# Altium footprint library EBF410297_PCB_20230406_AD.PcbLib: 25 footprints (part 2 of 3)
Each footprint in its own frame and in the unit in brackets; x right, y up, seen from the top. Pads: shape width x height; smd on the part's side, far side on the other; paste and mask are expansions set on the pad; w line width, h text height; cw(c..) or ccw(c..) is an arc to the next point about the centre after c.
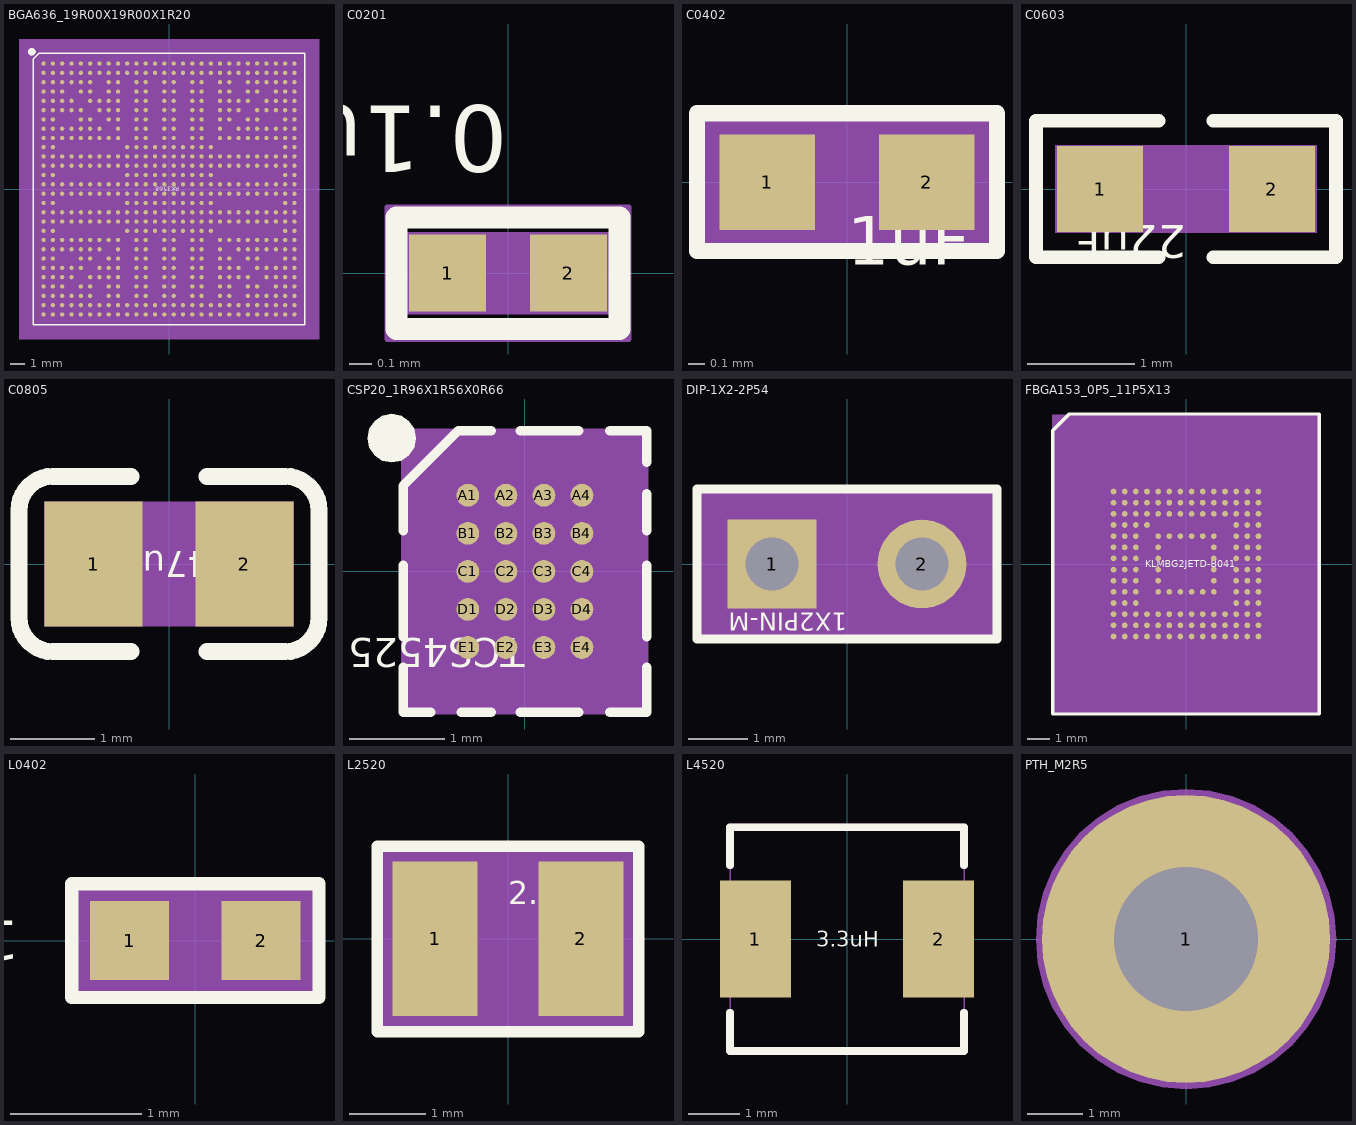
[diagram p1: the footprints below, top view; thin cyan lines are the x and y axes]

## BGA636_19R00X19R00X1R20 [mm] "BGA636_19R00X19R00X1R20"
pads (636):
  round 0.3 smd: A1(-8.78,8.78) A2(-8.13,8.78) A3(-7.48,8.78) A4(-6.82,8.78) A5(-6.17,8.78) A6(-5.52,8.78) A7(-4.87,8.78) A8(-4.22,8.78) A9(-3.57,8.78) A10(-2.93,8.78) A11(-2.28,8.78) A12(-1.63,8.78) A13(-0.98,8.78) A14(-0.33,8.78) A15(0.33,8.78) A16(0.98,8.78) A17(1.63,8.78) A18(2.28,8.78) A19(2.93,8.78) A20(3.57,8.78) A21(4.22,8.78) A22(4.87,8.78) A23(5.52,8.78) A24(6.17,8.78) A25(6.82,8.78) A26(7.48,8.78) A27(8.13,8.78) A28(8.78,8.78) AA1(-8.78,-4.22) AA2(-8.13,-4.22) AA3(-7.48,-4.22) AA4(-6.82,-4.22) AA5(-6.17,-4.22) AA6(-5.52,-4.22) AA7(-4.87,-4.22) AA9(-3.57,-4.22) AA11(-2.28,-4.22) AA12(-1.63,-4.22) AA14(-0.33,-4.22) AA15(0.33,-4.22) AA17(1.63,-4.22) AA18(2.28,-4.22) AA20(3.57,-4.22) AA22(4.87,-4.22) AA23(5.52,-4.22) AA24(6.17,-4.22) AA25(6.82,-4.22) AA26(7.48,-4.22) AA27(8.13,-4.22) AA28(8.78,-4.22) AB1(-8.78,-4.87) AB2(-8.13,-4.87) AB5(-6.17,-4.87) AB6(-5.52,-4.87) AB8(-4.22,-4.87) AB9(-3.57,-4.87) AB11(-2.28,-4.87) AB12(-1.63,-4.87) AB14(-0.33,-4.87) AB15(0.33,-4.87) AB17(1.63,-4.87) AB18(2.28,-4.87) AB20(3.57,-4.87) AB21(4.22,-4.87) AB23(5.52,-4.87) AB24(6.17,-4.87) AB27(8.13,-4.87) AB28(8.78,-4.87) AC1(-8.78,-5.52) AC2(-8.13,-5.52) AC3(-7.48,-5.52) AC4(-6.82,-5.52) AC5(-6.17,-5.52) AC7(-4.87,-5.52) AC8(-4.22,-5.52) AC9(-3.57,-5.52) AC11(-2.28,-5.52) AC12(-1.63,-5.52) AC14(-0.33,-5.52) AC15(0.33,-5.52) AC17(1.63,-5.52) AC18(2.28,-5.52) AC20(3.57,-5.52) AC21(4.22,-5.52) AC22(4.87,-5.52) AC24(6.17,-5.52) AC25(6.82,-5.52) AC26(7.48,-5.52) AC27(8.13,-5.52) AC28(8.78,-5.52) AD1(-8.78,-6.17) AD2(-8.13,-6.17) AD3(-7.48,-6.17) AD4(-6.82,-6.17) AD6(-5.52,-6.17) AD7(-4.87,-6.17) AD8(-4.22,-6.17) AD9(-3.57,-6.17) AD11(-2.28,-6.17) AD12(-1.63,-6.17) AD14(-0.33,-6.17) AD15(0.33,-6.17) AD17(1.63,-6.17) AD18(2.28,-6.17) AD20(3.57,-6.17) AD21(4.22,-6.17) AD22(4.87,-6.17) AD23(5.52,-6.17) AD25(6.82,-6.17) AD26(7.48,-6.17) AD27(8.13,-6.17) AD28(8.78,-6.17) AE1(-8.78,-6.82) AE2(-8.13,-6.82) AE3(-7.48,-6.82) AE5(-6.17,-6.82) AE6(-5.52,-6.82) AE8(-4.22,-6.82) AE9(-3.57,-6.82) AE11(-2.28,-6.82) AE12(-1.63,-6.82) AE14(-0.33,-6.82) AE15(0.33,-6.82) AE17(1.63,-6.82) AE18(2.28,-6.82) AE20(3.57,-6.82) AE21(4.22,-6.82) AE23(5.52,-6.82) AE24(6.17,-6.82) AE26(7.48,-6.82) AE27(8.13,-6.82) AE28(8.78,-6.82) AF1(-8.78,-7.48) AF2(-8.13,-7.48) AF3(-7.48,-7.48) AF4(-6.82,-7.48) AF5(-6.17,-7.48) AF6(-5.52,-7.48) AF8(-4.22,-7.48) AF9(-3.57,-7.48) AF11(-2.28,-7.48) AF12(-1.63,-7.48) AF14(-0.33,-7.48) AF15(0.33,-7.48) AF17(1.63,-7.48) AF18(2.28,-7.48) AF20(3.57,-7.48) AF21(4.22,-7.48) AF23(5.52,-7.48) AF24(6.17,-7.48) AF25(6.82,-7.48) AF26(7.48,-7.48) AF27(8.13,-7.48) AF28(8.78,-7.48) AG1(-8.78,-8.13) AG2(-8.13,-8.13) AG3(-7.48,-8.13) AG4(-6.82,-8.13) AG5(-6.17,-8.13) AG6(-5.52,-8.13) AG7(-4.87,-8.13) AG8(-4.22,-8.13) AG9(-3.57,-8.13) AG10(-2.93,-8.13) AG11(-2.28,-8.13) AG12(-1.63,-8.13) AG13(-0.98,-8.13) AG14(-0.33,-8.13) AG15(0.33,-8.13) AG16(0.98,-8.13) AG17(1.63,-8.13) AG18(2.28,-8.13) AG19(2.93,-8.13) AG20(3.57,-8.13) AG21(4.22,-8.13) AG22(4.87,-8.13) AG23(5.52,-8.13) AG24(6.17,-8.13) AG25(6.82,-8.13) AG26(7.48,-8.13) AG27(8.13,-8.13) AG28(8.78,-8.13) AH1(-8.78,-8.78) AH2(-8.13,-8.78) AH3(-7.48,-8.78) AH4(-6.82,-8.78) AH5(-6.17,-8.78) AH6(-5.52,-8.78) AH7(-4.87,-8.78) AH8(-4.22,-8.78) AH9(-3.57,-8.78) AH10(-2.93,-8.78) AH11(-2.28,-8.78) AH12(-1.63,-8.78) AH13(-0.98,-8.78) AH14(-0.33,-8.78) AH15(0.33,-8.78) AH16(0.98,-8.78) AH17(1.63,-8.78) AH18(2.28,-8.78) AH19(2.93,-8.78) AH20(3.57,-8.78) AH21(4.22,-8.78) AH22(4.87,-8.78) AH23(5.52,-8.78) AH24(6.17,-8.78) AH25(6.82,-8.78) AH26(7.48,-8.78) AH27(8.13,-8.78) AH28(8.78,-8.78) B1(-8.78,8.13) B2(-8.13,8.13) B3(-7.48,8.13) B4(-6.82,8.13) B5(-6.17,8.13) B6(-5.52,8.13) B7(-4.87,8.13) B8(-4.22,8.13) B9(-3.57,8.13) B10(-2.93,8.13) B11(-2.28,8.13) B12(-1.63,8.13) B13(-0.98,8.13) B14(-0.33,8.13) B15(0.33,8.13) B16(0.98,8.13) B17(1.63,8.13) B18(2.28,8.13) B19(2.93,8.13) B20(3.57,8.13) B21(4.22,8.13) B22(4.87,8.13) B23(5.52,8.13) B24(6.17,8.13) B25(6.82,8.13) B26(7.48,8.13) B27(8.13,8.13) B28(8.78,8.13) C1(-8.78,7.48) C2(-8.13,7.48) C3(-7.48,7.48) C4(-6.82,7.48) C5(-6.17,7.48) C6(-5.52,7.48) C8(-4.22,7.48) C9(-3.57,7.48) C11(-2.28,7.48) C12(-1.63,7.48) C14(-0.33,7.48) C15(0.33,7.48) C17(1.63,7.48) C18(2.28,7.48) C20(3.57,7.48) C21(4.22,7.48) C23(5.52,7.48) C24(6.17,7.48) C25(6.82,7.48) C26(7.48,7.48) C27(8.13,7.48) C28(8.78,7.48) D1(-8.78,6.82) D2(-8.13,6.82) D3(-7.48,6.82) D5(-6.17,6.82) D6(-5.52,6.82) D8(-4.22,6.82) D9(-3.57,6.82) D11(-2.28,6.82) D12(-1.63,6.82) D14(-0.33,6.82) D15(0.33,6.82) D17(1.63,6.82) D18(2.28,6.82) D20(3.57,6.82) D21(4.22,6.82) D23(5.52,6.82) D24(6.17,6.82) D26(7.48,6.82) D27(8.13,6.82) D28(8.78,6.82) E1(-8.78,6.17) E2(-8.13,6.17) E3(-7.48,6.17) E4(-6.82,6.17) E6(-5.52,6.17) E7(-4.87,6.17) E8(-4.22,6.17) E9(-3.57,6.17) E11(-2.28,6.17) E12(-1.63,6.17) E14(-0.33,6.17) E15(0.33,6.17) E17(1.63,6.17) E18(2.28,6.17) E20(3.57,6.17) E21(4.22,6.17) E22(4.87,6.17) E23(5.52,6.17) E25(6.82,6.17) E26(7.48,6.17) E27(8.13,6.17) E28(8.78,6.17) F1(-8.78,5.52) F2(-8.13,5.52) F3(-7.48,5.52) F4(-6.82,5.52) F5(-6.17,5.52) F7(-4.87,5.52) F8(-4.22,5.52) F9(-3.57,5.52) F11(-2.28,5.52) F12(-1.63,5.52) F14(-0.33,5.52) F15(0.33,5.52) F17(1.63,5.52) F18(2.28,5.52) F20(3.57,5.52) F21(4.22,5.52) F22(4.87,5.52) F24(6.17,5.52) F25(6.82,5.52) F26(7.48,5.52) F27(8.13,5.52) F28(8.78,5.52) G1(-8.78,4.87) G2(-8.13,4.87) G5(-6.17,4.87) G6(-5.52,4.87) G8(-4.22,4.87) G9(-3.57,4.87) G11(-2.28,4.87) G12(-1.63,4.87) G14(-0.33,4.87) G15(0.33,4.87) G17(1.63,4.87) G18(2.28,4.87) G20(3.57,4.87) G21(4.22,4.87) G23(5.52,4.87) G24(6.17,4.87) G27(8.13,4.87) G28(8.78,4.87) H1(-8.78,4.22) H2(-8.13,4.22) H3(-7.48,4.22) H4(-6.82,4.22) H5(-6.17,4.22) H6(-5.52,4.22) H7(-4.87,4.22) H9(-3.57,4.22) H11(-2.28,4.22) H12(-1.63,4.22) H14(-0.33,4.22) H15(0.33,4.22) H17(1.63,4.22) H18(2.28,4.22) H20(3.57,4.22) H22(4.87,4.22) H23(5.52,4.22) H24(6.17,4.22) H25(6.82,4.22) H26(7.48,4.22) H27(8.13,4.22) H28(8.78,4.22) J1(-8.78,3.57) J2(-8.13,3.57) J3(-7.48,3.57) J4(-6.82,3.57) J5(-6.17,3.57) J6(-5.52,3.57) J7(-4.87,3.57) J8(-4.22,3.57) J9(-3.57,3.57) J11(-2.28,3.57) J12(-1.63,3.57) J14(-0.33,3.57) J15(0.33,3.57) J17(1.63,3.57) J18(2.28,3.57) J20(3.57,3.57) J21(4.22,3.57) J22(4.87,3.57) J23(5.52,3.57) J24(6.17,3.57) J25(6.82,3.57) J26(7.48,3.57) J27(8.13,3.57) J28(8.78,3.57) K1(-8.78,2.93) K2(-8.13,2.93) K10(-2.93,2.93) K11(-2.28,2.93) K12(-1.63,2.93) K13(-0.98,2.93) K14(-0.33,2.93) K15(0.33,2.93) K16(0.98,2.93) K17(1.63,2.93) K18(2.28,2.93) K19(2.93,2.93) K27(8.13,2.93) K28(8.78,2.93) L1(-8.78,2.28) L2(-8.13,2.28) L3(-7.48,2.28) L4(-6.82,2.28) L5(-6.17,2.28) L6(-5.52,2.28) L7(-4.87,2.28) L8(-4.22,2.28) L9(-3.57,2.28) L10(-2.93,2.28) L11(-2.28,2.28) L12(-1.63,2.28) L13(-0.98,2.28) L14(-0.33,2.28) L15(0.33,2.28) L16(0.98,2.28) L17(1.63,2.28) L18(2.28,2.28) L19(2.93,2.28) L20(3.57,2.28) L21(4.22,2.28) L22(4.87,2.28) L23(5.52,2.28) L24(6.17,2.28) L25(6.82,2.28) L26(7.48,2.28) L27(8.13,2.28) L28(8.78,2.28) M1(-8.78,1.63) M2(-8.13,1.63) M3(-7.48,1.63) M4(-6.82,1.63) M5(-6.17,1.63) M6(-5.52,1.63) M7(-4.87,1.63) M8(-4.22,1.63) M9(-3.57,1.63) M10(-2.93,1.63) M11(-2.28,1.63) M12(-1.63,1.63) M13(-0.98,1.63) M14(-0.33,1.63) M15(0.33,1.63) M16(0.98,1.63) M17(1.63,1.63) M18(2.28,1.63) M19(2.93,1.63) M20(3.57,1.63) M21(4.22,1.63) M22(4.87,1.63) M23(5.52,1.63) M24(6.17,1.63) M25(6.82,1.63) M26(7.48,1.63) M27(8.13,1.63) M28(8.78,1.63) N1(-8.78,0.98) N2(-8.13,0.98) N10(-2.93,0.98) N11(-2.28,0.98) N12(-1.63,0.98) N13(-0.98,0.98) N14(-0.33,0.98) N15(0.33,0.98) N16(0.98,0.98) N17(1.63,0.98) N18(2.28,0.98) N19(2.93,0.98) N27(8.13,0.98) N28(8.78,0.98) P1(-8.78,0.33) P2(-8.13,0.33) P3(-7.48,0.33) P4(-6.82,0.33) P5(-6.17,0.33) P6(-5.52,0.33) P7(-4.87,0.33) P8(-4.22,0.33) P9(-3.57,0.33) P10(-2.93,0.33) P11(-2.28,0.33) P12(-1.63,0.33) P13(-0.98,0.33) P14(-0.33,0.33) P15(0.33,0.33) P16(0.98,0.33) P17(1.63,0.33) P18(2.28,0.33) P19(2.93,0.33) P20(3.57,0.33) P21(4.22,0.33) P22(4.87,0.33) P23(5.52,0.33) P24(6.17,0.33) P25(6.82,0.33) P26(7.48,0.33) P27(8.13,0.33) P28(8.78,0.33) R1(-8.78,-0.33) R2(-8.13,-0.33) R3(-7.48,-0.33) R4(-6.82,-0.33) R5(-6.17,-0.33) R6(-5.52,-0.33) R7(-4.87,-0.33) R8(-4.22,-0.33) R9(-3.57,-0.33) R10(-2.93,-0.33) R11(-2.28,-0.33) R12(-1.63,-0.33) R13(-0.98,-0.33) R14(-0.33,-0.33) R15(0.33,-0.33) R16(0.98,-0.33) R17(1.63,-0.33) R18(2.28,-0.33) R19(2.93,-0.33) R20(3.57,-0.33) R21(4.22,-0.33) R22(4.87,-0.33) R23(5.52,-0.33) R24(6.17,-0.33) R25(6.82,-0.33) R26(7.48,-0.33) R27(8.13,-0.33) R28(8.78,-0.33) T1(-8.78,-0.98) T2(-8.13,-0.98) T10(-2.93,-0.98) T11(-2.28,-0.98) T12(-1.63,-0.98) T13(-0.98,-0.98) T14(-0.33,-0.98) T15(0.33,-0.98) T16(0.98,-0.98) T17(1.63,-0.98) T18(2.28,-0.98) T19(2.93,-0.98) T27(8.13,-0.98) T28(8.78,-0.98) U1(-8.78,-1.63) U2(-8.13,-1.63) U3(-7.48,-1.63) U4(-6.82,-1.63) U5(-6.17,-1.63) U6(-5.52,-1.63) U7(-4.87,-1.63) U8(-4.22,-1.63) U9(-3.57,-1.63) U10(-2.93,-1.63) U11(-2.28,-1.63) U12(-1.63,-1.63) U13(-0.98,-1.63) U14(-0.33,-1.63) U15(0.33,-1.63) U16(0.98,-1.63) U17(1.63,-1.63) U18(2.28,-1.63) U19(2.93,-1.63) U20(3.57,-1.63) U21(4.22,-1.63) U22(4.87,-1.63) U23(5.52,-1.63) U24(6.17,-1.63) U25(6.82,-1.63) U26(7.48,-1.63) U27(8.13,-1.63) U28(8.78,-1.63) V1(-8.78,-2.28) V2(-8.13,-2.28) V3(-7.48,-2.28) V4(-6.82,-2.28) V5(-6.17,-2.28) V6(-5.52,-2.28) V7(-4.87,-2.28) V8(-4.22,-2.28) V9(-3.57,-2.28) V10(-2.93,-2.28) V11(-2.28,-2.28) V12(-1.63,-2.28) V13(-0.98,-2.28) V14(-0.33,-2.28) V15(0.33,-2.28) V16(0.98,-2.28) V17(1.63,-2.28) V18(2.28,-2.28) V19(2.93,-2.28) V20(3.57,-2.28) V21(4.22,-2.28) V22(4.87,-2.28) V23(5.52,-2.28) V24(6.17,-2.28) V25(6.82,-2.28) V26(7.48,-2.28) V27(8.13,-2.28) V28(8.78,-2.28) W1(-8.78,-2.93) W2(-8.13,-2.93) W10(-2.93,-2.93) W11(-2.28,-2.93) W12(-1.63,-2.93) W13(-0.98,-2.93) W14(-0.33,-2.93) W15(0.33,-2.93) W16(0.98,-2.93) W17(1.63,-2.93) W18(2.28,-2.93) W19(2.93,-2.93) W27(8.13,-2.93) W28(8.78,-2.93) Y1(-8.78,-3.57) Y2(-8.13,-3.57) Y3(-7.48,-3.57) Y4(-6.82,-3.57) Y5(-6.17,-3.57) Y6(-5.52,-3.57) Y7(-4.87,-3.57) Y8(-4.22,-3.57) Y9(-3.57,-3.57) Y11(-2.28,-3.57) Y12(-1.63,-3.57) Y14(-0.33,-3.57) Y15(0.33,-3.57) Y17(1.63,-3.57) Y18(2.28,-3.57) Y20(3.57,-3.57) Y21(4.22,-3.57) Y22(4.87,-3.57) Y23(5.52,-3.57) Y24(6.17,-3.57) Y25(6.82,-3.57) Y26(7.48,-3.57) Y27(8.13,-3.57) Y28(8.78,-3.57)
Top Overlay:
  dashed: -9.855,9.6 -9.836,9.502 -9.78,9.42 -9.698,9.364 -9.6,9.345 -9.502,9.364 -9.475,9.383 -9.42,9.42 -9.364,9.502 -9.345,9.6 -9.364,9.698 -9.42,9.78 -9.475,9.817 -9.502,9.836 -9.6,9.855 -9.698,9.836 -9.78,9.78 -9.836,9.698
  lines w0.13: -9.5,-9.5 9.5,-9.5 9.5,9.5 -9.1,9.5 -9.5,9.1 -9.5,-9.5
  text "RK3568" at 0.732,0.152 h0.3
Top 3D Body:
  region: -10.5,10.5 -10.5,-10.5 10.5,-10.5 10.5,10.5
Mechanical 14:
  text "F5" at -5.658,5.52 h0.64
  text "F8" at -3.708,5.52 h0.64
  text "F7" at -4.358,5.52 h0.64
  text "P7" at -4.358,0.33 h0.64
  text "P5" at -5.658,0.33 h0.64
  text "M4" at -6.308,1.63 h0.64
  text "M5" at -5.658,1.63 h0.64
  text "R5" at -5.658,-0.33 h0.64
  text "M7" at -4.358,1.63 h0.64
  text "R7" at -4.358,-0.33 h0.64
  text "P4" at -6.308,0.33 h0.64
  text "R4" at -6.308,-0.33 h0.64
  text "P1" at -8.268,0.33 h0.64
  text "P2" at -7.618,0.33 h0.64
  text "P8" at -3.708,0.33 h0.64
  text "M10" at -2.162,1.63 h0.64
  text "L10" at -2.162,2.28 h0.64
  text "K10" at -2.162,2.93 h0.64
  text "J11" at -1.512,3.57 h0.64
  text "J12" at -0.862,3.57 h0.64
  text "J14" at 0.438,3.57 h0.64
  text "AA22" at 5.894,-4.22 h0.64
  text "P27" at 8.898,0.33 h0.64
  text "P28" at 9.548,0.33 h0.64
  text "AC20" at 4.594,-5.52 h0.64
  text "AH24" at 7.194,-8.78 h0.64
  text "F2" at -7.618,5.52 h0.64
  text "AG12" at -0.606,-8.13 h0.64
  text "C27" at 8.898,7.48 h0.64
  text "E1" at -8.268,6.17 h0.64
  text "AF5" at -5.402,-7.48 h0.64
  text "AH12" at -0.606,-8.78 h0.64
  text "E2" at -7.618,6.17 h0.64
  text "AF6" at -4.752,-7.48 h0.64
  text "AG11" at -1.256,-8.13 h0.64
  text "D1" at -8.268,6.82 h0.64
  text "AH11" at -1.256,-8.78 h0.64
  text "L23" at 6.288,2.28 h0.64
  text "J1" at -8.268,3.57 h0.64
  text "AD6" at -4.752,-6.17 h0.64
  text "AE11" at -1.256,-6.82 h0.64
  text "E27" at 8.898,6.17 h0.64
  text "J2" at -7.618,3.57 h0.64
  text "AD11" at -1.256,-6.17 h0.64
  text "E28" at 9.548,6.17 h0.64
  text "H1" at -8.268,4.22 h0.64
  text "AD9" at -2.802,-6.17 h0.64
  text "B28" at 9.548,8.13 h0.64
  text "M24" at 6.938,1.63 h0.64
  text "H4" at -6.308,4.22 h0.64
  text "AE9" at -2.802,-6.82 h0.64
  text "AG10" at -1.906,-8.13 h0.64
  text "AH10" at -1.906,-8.78 h0.64
  text "P24" at 6.938,0.33 h0.64
  text "AG9" at -2.802,-8.13 h0.64
  text "P25" at 7.588,0.33 h0.64
  text "AH9" at -2.802,-8.78 h0.64
  text "C28" at 9.548,7.48 h0.64
  text "H5" at -5.658,4.22 h0.64
  text "G1" at -8.268,4.87 h0.64
  text "G2" at -7.618,4.87 h0.64
  text "AG4" at -6.052,-8.13 h0.64
  text "D27" at 8.898,6.82 h0.64
  text "AF4" at -6.052,-7.48 h0.64
  text "AH3" at -6.712,-8.78 h0.64
  text "AF27" at 9.154,-7.48 h0.64
  text "AG3" at -6.712,-8.13 h0.64
  text "AF28" at 9.804,-7.48 h0.64
  text "D26" at 8.248,6.82 h0.64
  text "E25" at 7.588,6.17 h0.64
  text "M1" at -8.268,1.63 h0.64
  text "AD18" at 3.304,-6.17 h0.64
  text "AE18" at 3.304,-6.82 h0.64
  text "AG1" at -8.012,-8.13 h0.64
  text "AD17" at 2.654,-6.17 h0.64
  text "N2" at -7.618,0.98 h0.64
  text "P10" at -2.162,0.33 h0.64
  text "AF2" at -7.362,-7.48 h0.64
  text "AC17" at 2.654,-5.52 h0.64
  text "L7" at -4.358,2.28 h0.64
  text "P9" at -3.058,0.33 h0.64
  text "AF1" at -8.012,-7.48 h0.64
  text "AD14" at 0.694,-6.17 h0.64
  text "L6" at -5.008,2.28 h0.64
  text "R8" at -3.708,-0.33 h0.64
  text "AC14" at 0.694,-5.52 h0.64
  text "K2" at -7.618,2.93 h0.64
  text "AD12" at -0.606,-6.17 h0.64
  text "F28" at 9.548,5.52 h0.64
  text "J6" at -5.008,3.57 h0.64
  text "AE1" at -8.012,-6.82 h0.64
  text "AE12" at -0.606,-6.82 h0.64
  text "G27" at 8.898,4.87 h0.64
  text "J7" at -4.358,3.57 h0.64
  text "AD15" at 1.354,-6.17 h0.64
  text "G28" at 9.548,4.87 h0.64
  text "L4" at -6.308,2.28 h0.64
  text "C21" at 4.988,7.48 h0.64
  text "M15" at 1.098,1.63 h0.64
  text "AE15" at 1.354,-6.82 h0.64
  text "B24" at 6.938,8.13 h0.64
  text "D21" at 4.988,6.82 h0.64
  text "J4" at -6.308,3.57 h0.64
  text "A25" at 7.588,8.78 h0.64
  text "E21" at 4.988,6.17 h0.64
  text "AD4" at -6.052,-6.17 h0.64
  text "AC5" at -5.402,-5.52 h0.64
  text "T28" at 9.548,-0.98 h0.64
  text "E22" at 5.638,6.17 h0.64
  text "L2" at -7.618,2.28 h0.64
  text "P22" at 5.638,0.33 h0.64
  text "AA6" at -4.752,-4.22 h0.64
  text "T27" at 8.898,-0.98 h0.64
  text "B25" at 7.588,8.13 h0.64
  text "L1" at -8.268,2.28 h0.64
  text "P23" at 6.288,0.33 h0.64
  text "AD2" at -7.362,-6.17 h0.64
  text "AB5" at -5.402,-4.87 h0.64
  text "R28" at 9.548,-0.33 h0.64
  text "B22" at 5.638,8.13 h0.64
  text "M23" at 6.288,1.63 h0.64
  text "AB1" at -8.012,-4.87 h0.64
  text "R27" at 8.898,-0.33 h0.64
  text "Y7" at -4.358,-3.57 h0.64
  text "F27" at 8.898,5.52 h0.64
  text "AC24" at 7.194,-5.52 h0.64
  text "A23" at 6.288,8.78 h0.64
  text "H25" at 7.588,4.22 h0.64
  text "V28" at 9.548,-2.28 h0.64
  text "J15" at 1.098,3.57 h0.64
  text "K15" at 1.098,2.93 h0.64
  text "L15" at 1.098,2.28 h0.64
  text "L16" at 1.748,2.28 h0.64
  text "K16" at 1.748,2.93 h0.64
  text "K17" at 2.398,2.93 h0.64
  text "K18" at 3.048,2.93 h0.64
  text "L17" at 2.398,2.28 h0.64
  text "L18" at 3.048,2.28 h0.64
  text "M17" at 2.398,1.63 h0.64
  text "J28" at 9.548,3.57 h0.64
  text "F24" at 6.938,5.52 h0.64
  text "V27" at 8.898,-2.28 h0.64
  text "K27" at 8.898,2.93 h0.64
  text "U28" at 9.548,-1.63 h0.64
  text "U27" at 8.898,-1.63 h0.64
  text "B10" at -2.162,8.13 h0.64
  text "W14" at 0.438,-2.93 h0.64
  text "A9" at -3.058,8.78 h0.64
  text "Y14" at 0.438,-3.57 h0.64
  text "A26" at 8.248,8.78 h0.64
  text "D12" at -0.862,6.82 h0.64
  text "AC1" at -8.012,-5.52 h0.64
  text "E12" at -0.862,6.17 h0.64
  text "A12" at -0.862,8.78 h0.64
  text "D15" at 1.098,6.82 h0.64
  text "E15" at 1.098,6.17 h0.64
  text "E14" at 0.438,6.17 h0.64
  text "F25" at 7.588,5.52 h0.64
  text "H24" at 6.938,4.22 h0.64
  text "A22" at 5.638,8.78 h0.64
  text "D14" at 0.438,6.82 h0.64
  text "V24" at 6.938,-2.28 h0.64
  text "V25" at 7.588,-2.28 h0.64
  text "A11" at -1.512,8.78 h0.64
  text "H23" at 6.288,4.22 h0.64
  text "B11" at -1.512,8.13 h0.64
  text "W16" at 1.748,-2.93 h0.64
  text "Y17" at 2.398,-3.57 h0.64
  text "F26" at 8.248,5.52 h0.64
  text "E26" at 8.248,6.17 h0.64
  text "A16" at 1.748,8.78 h0.64
  text "W15" at 1.098,-2.93 h0.64
  text "K28" at 9.548,2.93 h0.64
  text "B17" at 2.398,8.13 h0.64
  text "Y15" at 1.098,-3.57 h0.64
  text "L27" at 8.898,2.28 h0.64
  text "A17" at 2.398,8.78 h0.64
  text "L28" at 9.548,2.28 h0.64
  text "B18" at 3.048,8.13 h0.64
  text "M27" at 8.898,1.63 h0.64
  text "B13" at -0.212,8.13 h0.64
  text "M28" at 9.548,1.63 h0.64
  text "A13" at -0.212,8.78 h0.64
  text "N27" at 8.898,0.98 h0.64
  text "Y6" at -5.008,-3.57 h0.64
  text "D17" at 2.398,6.82 h0.64
  text "Y5" at -5.658,-3.57 h0.64
  text "B14" at 0.438,8.13 h0.64
  text "AA3" at -6.712,-4.22 h0.64
  text "H18" at 3.048,4.22 h0.64
  text "AF8" at -3.452,-7.48 h0.64
  text "AA11" at -1.256,-4.22 h0.64
  text "E17" at 2.398,6.17 h0.64
  text "B15" at 1.098,8.13 h0.64
  text "AD8" at -3.452,-6.17 h0.64
  text "A15" at 1.098,8.78 h0.64
  text "AE8" at -3.452,-6.82 h0.64
  text "B6" at -5.008,8.13 h0.64
  text "AG8" at -3.452,-8.13 h0.64
  text "AA2" at -7.362,-4.22 h0.64
  text "B1" at -8.268,8.13 h0.64
  text "A19" at 3.698,8.78 h0.64
  text "Y4" at -6.308,-3.57 h0.64
  text "F4" at -6.308,5.52 h0.64
  text "B19" at 3.698,8.13 h0.64
  text "Y3" at -6.968,-3.57 h0.64
  text "AG7" at -4.102,-8.13 h0.64
  text "A20" at 4.338,8.78 h0.64
  text "AH6" at -4.752,-8.78 h0.64
  text "H28" at 9.548,4.22 h0.64
  text "B20" at 4.338,8.13 h0.64
  text "R2" at -7.618,-0.33 h0.64
  text "B21" at 4.988,8.13 h0.64
  text "R1" at -8.268,-0.33 h0.64
  text "J25" at 7.588,3.57 h0.64
  text "D9" at -3.058,6.82 h0.64
  text "C20" at 4.338,7.48 h0.64
  text "J24" at 6.938,3.57 h0.64
  text "H26" at 8.248,4.22 h0.64
  text "T2" at -7.618,-0.98 h0.64
  text "J23" at 6.288,3.57 h0.64
  text "T1" at -8.268,-0.98 h0.64
  text "H27" at 8.898,4.22 h0.64
  text "B7" at -4.358,8.13 h0.64
  text "D18" at 3.048,6.82 h0.64
  text "A7" at -4.358,8.78 h0.64
  text "E18" at 3.048,6.17 h0.64
  text "A8" at -3.708,8.78 h0.64
  text "Y1" at -8.268,-3.57 h0.64
  text "J21" at 4.988,3.57 h0.64
  text "H20" at 4.338,4.22 h0.64
  text "R9" at -3.058,-0.33 h0.64
  text "U9" at -3.058,-1.63 h0.64
  text "Y2" at -7.618,-3.57 h0.64
  text "L25" at 7.588,2.28 h0.64
  text "W2" at -7.618,-2.93 h0.64
  text "M25" at 7.588,1.63 h0.64
  text "C1" at -8.268,7.48 h0.64
  text "W1" at -8.268,-2.93 h0.64
  text "A5" at -5.658,8.78 h0.64
  text "V7" at -4.358,-2.28 h0.64
  text "D6" at -5.008,6.82 h0.64
  text "C2" at -7.618,7.48 h0.64
  text "V2" at -7.618,-2.28 h0.64
  text "V10" at -2.162,-2.28 h0.64
  text "V11" at -1.512,-2.28 h0.64
  text "V12" at -0.862,-2.28 h0.64
  text "V4" at -6.308,-2.28 h0.64
  text "AG24" at 7.194,-8.13 h0.64
  text "AB20" at 4.594,-4.87 h0.64
  text "V1" at -8.268,-2.28 h0.64
  text "AG26" at 8.504,-8.13 h0.64
  text "C4" at -6.308,7.48 h0.64
  text "B8" at -3.708,8.13 h0.64
  text "U5" at -5.658,-1.63 h0.64
  text "C5" at -5.658,7.48 h0.64
  text "E4" at -6.308,6.17 h0.64
  text "U4" at -6.308,-1.63 h0.64
  text "AH27" at 9.154,-8.78 h0.64
  text "A6" at -5.008,8.78 h0.64
  text "L14" at 0.438,2.28 h0.64
  text "R10" at -2.162,-0.33 h0.64
  text "AC18" at 3.304,-5.52 h0.64
  text "D28" at 9.548,6.82 h0.64
  text "B23" at 6.288,8.13 h0.64
  text "AA26" at 8.504,-4.22 h0.64
  text "AB24" at 7.194,-4.87 h0.64
  text "AA24" at 7.194,-4.22 h0.64
  text "AA23" at 6.544,-4.22 h0.64
  text "Y23" at 6.288,-3.57 h0.64
  text "Y24" at 6.938,-3.57 h0.64
  text "AC26" at 8.504,-5.52 h0.64
  text "AC25" at 7.844,-5.52 h0.64
  text "AE14" at 0.694,-6.82 h0.64
  text "AE17" at 2.654,-6.82 h0.64
  text "AF17" at 2.654,-7.48 h0.64
  text "AF18" at 3.304,-7.48 h0.64
  text "AG18" at 3.304,-8.13 h0.64
  text "AF20" at 4.594,-7.48 h0.64
  text "AF21" at 5.244,-7.48 h0.64
  text "AE21" at 5.244,-6.82 h0.64
  text "AE20" at 4.594,-6.82 h0.64
  text "AH18" at 3.304,-8.78 h0.64
  text "AF26" at 8.504,-7.48 h0.64
  text "AE28" at 9.804,-6.82 h0.64
  text "AE27" at 9.154,-6.82 h0.64
  text "R23" at 6.288,-0.33 h0.64
  text "AA17" at 2.654,-4.22 h0.64
  text "AB17" at 2.654,-4.87 h0.64
  text "Y18" at 3.048,-3.57 h0.64
  text "W17" at 2.398,-2.93 h0.64
  text "V20" at 4.338,-2.28 h0.64
  text "V22" at 5.638,-2.28 h0.64
  text "U17" at 2.398,-1.63 h0.64
  text "U18" at 3.048,-1.63 h0.64
  text "T17" at 2.398,-0.98 h0.64
  text "T18" at 3.048,-0.98 h0.64
  text "R17" at 2.398,-0.33 h0.64
  text "R18" at 3.048,-0.33 h0.64
  text "T19" at 3.698,-0.98 h0.64
  text "R19" at 3.698,-0.33 h0.64
  text "AH23" at 6.544,-8.78 h0.64
  text "AA15" at 1.354,-4.22 h0.64
  text "AB15" at 1.354,-4.87 h0.64
  text "AC15" at 1.354,-5.52 h0.64
  text "AB14" at 0.694,-4.87 h0.64
  text "AA14" at 0.694,-4.22 h0.64
  text "AF12" at -0.606,-7.48 h0.64
  text "AF11" at -1.256,-7.48 h0.64
  text "AF9" at -2.802,-7.48 h0.64
  text "AC12" at -0.606,-5.52 h0.64
  text "AB12" at -0.606,-4.87 h0.64
  text "AB11" at -1.256,-4.87 h0.64
  text "AC11" at -1.256,-5.52 h0.64
  text "Y12" at -0.862,-3.57 h0.64
  text "AA12" at -0.606,-4.22 h0.64
  text "Y11" at -1.512,-3.57 h0.64
  text "W11" at -1.512,-2.93 h0.64
  text "W10" at -2.162,-2.93 h0.64
  text "W12" at -0.862,-2.93 h0.64
  text "W13" at -0.212,-2.93 h0.64
  text "V13" at -0.212,-2.28 h0.64
  text "V16" at 1.748,-2.28 h0.64
  text "U16" at 1.748,-1.63 h0.64
  text "U15" at 1.098,-1.63 h0.64
  text "V15" at 1.098,-2.28 h0.64
  text "U14" at 0.438,-1.63 h0.64
  text "V14" at 0.438,-2.28 h0.64
  text "T15" at 1.098,-0.98 h0.64
  text "R15" at 1.098,-0.33 h0.64
  text "T14" at 0.438,-0.98 h0.64
  text "R14" at 0.438,-0.33 h0.64
  text "U10" at -2.162,-1.63 h0.64
  text "R11" at -1.512,-0.33 h0.64
  text "T11" at -1.512,-0.98 h0.64
  text "T10" at -2.162,-0.98 h0.64
  text "AA4" at -6.052,-4.22 h0.64
  text "AD3" at -6.712,-6.17 h0.64
  text "AE6" at -4.752,-6.82 h0.64
  text "AH8" at -3.452,-8.78 h0.64
  text "AG5" at -5.402,-8.13 h0.64
  text "AC9" at -2.802,-5.52 h0.64
  text "Y9" at -3.058,-3.57 h0.64
  text "AA9" at -2.802,-4.22 h0.64
  text "AB6" at -4.752,-4.87 h0.64
  text "Y8" at -3.708,-3.57 h0.64
  text "AB2" at -7.362,-4.87 h0.64
  text "N14" at 0.438,0.98 h0.64
  text "B26" at 8.248,8.13 h0.64
  text "C25" at 7.588,7.48 h0.64
  text "V23" at 6.288,-2.28 h0.64
  text "U23" at 6.288,-1.63 h0.64
  text "P21" at 4.988,0.33 h0.64
  text "M21" at 4.988,1.63 h0.64
  text "L24" at 6.938,2.28 h0.64
  text "L26" at 8.248,2.28 h0.64
  text "M26" at 8.248,1.63 h0.64
  text "G24" at 6.938,4.87 h0.64
  text "J22" at 5.638,3.57 h0.64
  text "K19" at 3.698,2.93 h0.64
  text "L19" at 3.698,2.28 h0.64
  text "L20" at 4.338,2.28 h0.64
  text "L21" at 4.988,2.28 h0.64
  text "J20" at 4.338,3.57 h0.64
  text "J18" at 3.048,3.57 h0.64
  text "J17" at 2.398,3.57 h0.64
  text "G18" at 3.048,4.87 h0.64
  text "G17" at 2.398,4.87 h0.64
  text "F17" at 2.398,5.52 h0.64
  text "M18" at 3.048,1.63 h0.64
  text "N18" at 3.048,0.98 h0.64
  text "N17" at 2.398,0.98 h0.64
  text "P17" at 2.398,0.33 h0.64
  text "N15" at 1.098,0.98 h0.64
  text "M16" at 1.748,1.63 h0.64
  text "P14" at 0.438,0.33 h0.64
  text "P12" at -0.862,0.33 h0.64
  text "N11" at -1.512,0.98 h0.64
  text "N12" at -0.862,0.98 h0.64
  text "M11" at -1.512,1.63 h0.64
  text "M13" at -0.212,1.63 h0.64
  text "M14" at 0.438,1.63 h0.64
  text "L13" at -0.212,2.28 h0.64
  text "K12" at -0.862,2.93 h0.64
  text "K14" at 0.438,2.93 h0.64
  text "K13" at -0.212,2.93 h0.64
  text "K11" at -1.512,2.93 h0.64
  text "G12" at -0.862,4.87 h0.64
  text "J8" at -3.708,3.57 h0.64
  text "L8" at -3.708,2.28 h0.64
  text "M8" at -3.708,1.63 h0.64
  text "M6" at -5.008,1.63 h0.64
  text "R6" at -5.008,-0.33 h0.64
  text "P6" at -5.008,0.33 h0.64
  text "V9" at -3.058,-2.28 h0.64
  text "V8" at -3.708,-2.28 h0.64
  text "U8" at -3.708,-1.63 h0.64
  text "U6" at -5.008,-1.63 h0.64
  text "V3" at -6.968,-2.28 h0.64
  text "U1" at -8.268,-1.63 h0.64
  text "P3" at -6.968,0.33 h0.64
  text "R3" at -6.968,-0.33 h0.64
  text "N1" at -8.268,0.98 h0.64
  text "M2" at -7.618,1.63 h0.64
  text "M3" at -6.968,1.63 h0.64
  text "L5" at -5.658,2.28 h0.64
  text "L3" at -6.968,2.28 h0.64
  text "K1" at -8.268,2.93 h0.64
  text "G8" at -3.708,4.87 h0.64
  text "G9" at -3.058,4.87 h0.64
  text "F9" at -3.058,5.52 h0.64
  text "E7" at -4.358,6.17 h0.64
  text "H6" at -5.008,4.22 h0.64
  text "G6" at -5.008,4.87 h0.64
  text "G5" at -5.658,4.87 h0.64
  text "F1" at -8.268,5.52 h0.64
  text "J5" at -5.658,3.57 h0.64
  text "J3" at -6.968,3.57 h0.64
  text "H3" at -6.968,4.22 h0.64
  text "H2" at -7.618,4.22 h0.64
  text "C6" at -5.008,7.48 h0.64
  text "E3" at -6.968,6.17 h0.64
  text "F3" at -6.968,5.52 h0.64
  text "D2" at -7.618,6.82 h0.64
  text "D3" at -6.968,6.82 h0.64
  text "C3" at -6.968,7.48 h0.64
  text "A1" at -8.268,8.78 h0.64
  text "B5" at -5.658,8.13 h0.64
  text "A3" at -6.968,8.78 h0.64
  text "C9" at -3.058,7.48 h0.64
  text "C8" at -3.708,7.48 h0.64
  text "B9" at -3.058,8.13 h0.64
  text "C11" at -1.512,7.48 h0.64
  text "D11" at -1.512,6.82 h0.64
  text "C12" at -0.862,7.48 h0.64
  text "B12" at -0.862,8.13 h0.64
  text "C15" at 1.098,7.48 h0.64
  text "G11" at -1.512,4.87 h0.64
  text "G14" at 0.438,4.87 h0.64
  text "F14" at 0.438,5.52 h0.64
  text "G15" at 1.098,4.87 h0.64
  text "F15" at 1.098,5.52 h0.64
  text "A10" at -2.162,8.78 h0.64
  text "A14" at 0.438,8.78 h0.64
  text "B16" at 1.748,8.13 h0.64
  text "C17" at 2.398,7.48 h0.64
  text "U26" at 8.248,-1.63 h0.64
  text "V26" at 8.248,-2.28 h0.64
  text "R26" at 8.248,-0.33 h0.64
  text "AH28" at 9.804,-8.78 h0.64
  text "U7" at -4.358,-1.63 h0.64
  text "P15" at 1.098,0.33 h0.64
  text "L11" at -1.512,2.28 h0.64
  text "AD26" at 8.504,-6.17 h0.64
  text "P26" at 8.248,0.33 h0.64
  text "N28" at 9.548,0.98 h0.64
  text "AH1" at -8.012,-8.78 h0.64
  text "AF3" at -6.712,-7.48 h0.64
  text "J26" at 8.248,3.57 h0.64
  text "J27" at 8.898,3.57 h0.64
  text "A28" at 9.548,8.78 h0.64
  text "C14" at 0.438,7.48 h0.64
  text "Y26" at 8.248,-3.57 h0.64
  text "C18" at 3.048,7.48 h0.64
  text "A18" at 3.048,8.78 h0.64
  text "F12" at -0.862,5.52 h0.64
  text "AF14" at 0.694,-7.48 h0.64
  text "AF15" at 1.354,-7.48 h0.64
  text "H22" at 5.638,4.22 h0.64
  text "R22" at 5.638,-0.33 h0.64
  text "U22" at 5.638,-1.63 h0.64
  text "N10" at -2.162,0.98 h0.64
  text "AG22" at 5.894,-8.13 h0.64
  text "AH22" at 5.894,-8.78 h0.64
  text "AA28" at 9.804,-4.22 h0.64
  text "L12" at -0.862,2.28 h0.64
  text "M12" at -0.862,1.63 h0.64
  text "P13" at -0.212,0.33 h0.64
  text "N13" at -0.212,0.98 h0.64
  text "N16" at 1.748,0.98 h0.64
  text "P16" at 1.748,0.33 h0.64
  text "T16" at 1.748,-0.98 h0.64
  text "R16" at 1.748,-0.33 h0.64
  text "R12" at -0.862,-0.33 h0.64
  text "T12" at -0.862,-0.98 h0.64
  text "AG21" at 5.244,-8.13 h0.64
  text "AA27" at 9.154,-4.22 h0.64
  text "U11" at -1.512,-1.63 h0.64
  text "U12" at -0.862,-1.63 h0.64
  text "U13" at -0.212,-1.63 h0.64
  text "T13" at -0.212,-0.98 h0.64
  text "R13" at -0.212,-0.33 h0.64
  text "AH21" at 5.244,-8.78 h0.64
  text "D5" at -5.658,6.82 h0.64
  text "P18" at 3.048,0.33 h0.64
  text "P19" at 3.698,0.33 h0.64
  text "P20" at 4.338,0.33 h0.64
  text "N19" at 3.698,0.98 h0.64
  text "M19" at 3.698,1.63 h0.64
  text "AG20" at 4.594,-8.13 h0.64
  text "U2" at -7.618,-1.63 h0.64
  text "E23" at 6.288,6.17 h0.64
  text "E6" at -5.008,6.17 h0.64
  text "AH20" at 4.594,-8.78 h0.64
  text "G21" at 4.988,4.87 h0.64
  text "E11" at -1.512,6.17 h0.64
  text "M22" at 5.638,1.63 h0.64
  text "W18" at 3.048,-2.93 h0.64
  text "AH19" at 3.954,-8.78 h0.64
  text "F22" at 5.638,5.52 h0.64
  text "E9" at -3.058,6.17 h0.64
  text "Y21" at 4.988,-3.57 h0.64
  text "AG19" at 3.954,-8.13 h0.64
  text "G20" at 4.338,4.87 h0.64
  text "AB28" at 9.804,-4.87 h0.64
  text "Y20" at 4.338,-3.57 h0.64
  text "W19" at 3.698,-2.93 h0.64
  text "F21" at 4.988,5.52 h0.64
  text "AB27" at 9.154,-4.87 h0.64
  text "L22" at 5.638,2.28 h0.64
  text "B3" at -6.968,8.13 h0.64
  text "H17" at 2.398,4.22 h0.64
  text "V19" at 3.698,-2.28 h0.64
  text "V21" at 4.988,-2.28 h0.64
  text "P11" at -1.512,0.33 h0.64
  text "U21" at 4.988,-1.63 h0.64
  text "U20" at 4.338,-1.63 h0.64
  text "R20" at 4.338,-0.33 h0.64
  text "R21" at 4.988,-0.33 h0.64
  text "M20" at 4.338,1.63 h0.64
  text "V18" at 3.048,-2.28 h0.64
  text "V17" at 2.398,-2.28 h0.64
  text "B4" at -6.308,8.13 h0.64
  text "AC28" at 9.804,-5.52 h0.64
  text "A4" at -6.308,8.78 h0.64
  text "AC27" at 9.154,-5.52 h0.64
  text "AD28" at 9.804,-6.17 h0.64
  text "AD27" at 9.154,-6.17 h0.64
  text "Y25" at 7.588,-3.57 h0.64
  text "AG25" at 7.844,-8.13 h0.64
  text "AA25" at 7.844,-4.22 h0.64
  text "A2" at -7.618,8.78 h0.64
  text "U19" at 3.698,-1.63 h0.64
  text "B2" at -7.618,8.13 h0.64
  text "E8" at -3.708,6.17 h0.64
  text "D8" at -3.708,6.82 h0.64
  text "F11" at -1.512,5.52 h0.64
  text "H7" at -4.358,4.22 h0.64
  text "AB18" at 3.304,-4.87 h0.64
  text "AG28" at 9.804,-8.13 h0.64
  text "H15" at 1.098,4.22 h0.64
  text "H14" at 0.438,4.22 h0.64
  text "H11" at -1.512,4.22 h0.64
  text "H12" at -0.862,4.22 h0.64
  text "J9" at -3.058,3.57 h0.64
  text "H9" at -3.058,4.22 h0.64
  text "L9" at -3.058,2.28 h0.64
  text "M9" at -3.058,1.63 h0.64
  text "AA18" at 3.304,-4.22 h0.64
  text "AB23" at 6.544,-4.87 h0.64
  text "AE26" at 8.504,-6.82 h0.64
  text "AA20" at 4.594,-4.22 h0.64
  text "AD25" at 7.844,-6.17 h0.64
  text "F18" at 3.048,5.52 h0.64
  text "D20" at 4.338,6.82 h0.64
  text "D24" at 6.938,6.82 h0.64
  text "B27" at 8.898,8.13 h0.64
  text "Y22" at 5.638,-3.57 h0.64
  text "V6" at -5.008,-2.28 h0.64
  text "V5" at -5.658,-2.28 h0.64
  text "AH26" at 8.504,-8.78 h0.64
  text "Y27" at 8.898,-3.57 h0.64
  text "W27" at 8.898,-2.93 h0.64
  text "W28" at 9.548,-2.93 h0.64
  text "Y28" at 9.548,-3.57 h0.64
  text "C24" at 6.938,7.48 h0.64
  text "A27" at 8.898,8.78 h0.64
  text "D23" at 6.288,6.82 h0.64
  text "F20" at 4.338,5.52 h0.64
  text "C23" at 6.288,7.48 h0.64
  text "AF24" at 7.194,-7.48 h0.64
  text "AB21" at 5.244,-4.87 h0.64
  text "AC3" at -6.712,-5.52 h0.64
  text "AC2" at -7.362,-5.52 h0.64
  text "AE5" at -5.402,-6.82 h0.64
  text "AF25" at 7.844,-7.48 h0.64
  text "AE24" at 7.194,-6.82 h0.64
  text "AD22" at 5.894,-6.17 h0.64
  text "AC21" at 5.244,-5.52 h0.64
  text "AC22" at 5.894,-5.52 h0.64
  text "AH25" at 7.844,-8.78 h0.64
  text "AF23" at 6.544,-7.48 h0.64
  text "C26" at 8.248,7.48 h0.64
  text "AG6" at -4.752,-8.13 h0.64
  text "AD7" at -4.102,-6.17 h0.64
  text "AC7" at -4.102,-5.52 h0.64
  text "AC8" at -3.452,-5.52 h0.64
  text "AH5" at -5.402,-8.78 h0.64
  text "A21" at 4.988,8.78 h0.64
  text "E20" at 4.338,6.17 h0.64
  text "AH2" at -7.362,-8.78 h0.64
  text "AE2" at -7.362,-6.82 h0.64
  text "AA5" at -5.402,-4.22 h0.64
  text "AB8" at -3.452,-4.87 h0.64
  text "AE3" at -6.712,-6.82 h0.64
  text "AH16" at 2.004,-8.78 h0.64
  text "AA7" at -4.102,-4.22 h0.64
  text "AH17" at 2.654,-8.78 h0.64
  text "AC4" at -6.052,-5.52 h0.64
  text "AG16" at 2.004,-8.13 h0.64
  text "AD1" at -8.012,-6.17 h0.64
  text "AG17" at 2.654,-8.13 h0.64
  text "AA1" at -8.012,-4.22 h0.64
  text "AH4" at -6.052,-8.78 h0.64
  text "AG15" at 1.354,-8.13 h0.64
  text "AH15" at 1.354,-8.78 h0.64
  text "AG2" at -7.362,-8.13 h0.64
  text "AB9" at -2.802,-4.87 h0.64
  text "AH13" at 0.044,-8.78 h0.64
  text "AH14" at 0.694,-8.78 h0.64
  text "AG14" at 0.694,-8.13 h0.64
  text "A24" at 6.938,8.78 h0.64
  text "AD21" at 5.244,-6.17 h0.64
  text "AE23" at 6.544,-6.82 h0.64
  text "AD23" at 6.544,-6.17 h0.64
  text "AG27" at 9.154,-8.13 h0.64
  text "U3" at -6.968,-1.63 h0.64
  text "G23" at 6.288,4.87 h0.64
  text "U24" at 6.938,-1.63 h0.64
  text "U25" at 7.588,-1.63 h0.64
  text "R25" at 7.588,-0.33 h0.64
  text "R24" at 6.938,-0.33 h0.64
  text "AG13" at 0.044,-8.13 h0.64
  text "AG23" at 6.544,-8.13 h0.64
  text "AD20" at 4.594,-6.17 h0.64
  text "AH7" at -4.102,-8.78 h0.64
3D body: height 3.81, standoff 0, extent -10.5,-10.5 10.5,10.5

## C0201 [mm] "C0201"
pads (2):
  rect 0.35x0.35 smd: 1(-0.275,0) 2(0.275,0)
Top Overlay:
  lines w0.102: -0.508,-0.254 -0.508,0.254 0.508,0.254 0.508,-0.254 -0.508,-0.254
  text "0.1uF" at 0,0.762 h0.3
Top 3D Body:
  region: -0.475,-0.175 -0.475,0.175 0.475,0.175 0.475,-0.175
Mechanical 14:
  text "1" at -0.275,0.305 h0.76
  text "2" at 0.275,0.305 h0.76
Top Assembly:
  lines w0.025: -0.55,-0.3 0.55,-0.3 0.55,0.3 -0.55,0.3 -0.55,-0.3 ; -0.475,-0.175 0.475,-0.175 0.475,0.175 -0.475,0.175 -0.475,-0.175
  text "0.1uF" at 0.762,-0.254 h0.76
  text ".Designator" at 0.508,0.254 h0.76
3D body: height 3.81, standoff 0, extent -0.475,-0.175 0.475,0.175

## C0402 [mm] "C0402"
pads (2):
  rect 0.599x0.599 smd: 1(-0.5,0) 2(0.5,0)
Top Overlay:
  lines w0.102: -0.94,-0.432 0.94,-0.432 0.94,0.432 -0.94,0.432 -0.94,-0.432
  text "1uF" at 0,-0.518 h0.3
Top 3D Body:
  region: 0.94,0.432 0.94,-0.432 -0.94,-0.432 -0.94,0.432
Mechanical 14:
  text "1" at -0.5,-0.254 h0.64
  text "2" at 0.5,-0.254 h0.64
Top Assembly:
  dashed: -0.94,-0.432 -0.94,0.432 0.94,0.432 0.94,-0.432
3D body: height 3.81, standoff 0, extent -0.94,-0.432 0.94,0.432

## C0603 [mil] "C0603"
pads (2):
  rect 31.5x31.5 smd: 1(-31.5,0) 2(31.5,0)
Top Overlay:
  lines w5: -10,-25 -55,-25 -55,25 -10,25 ; 10,-25 55,-25 55,25 10,25
  text "22uF" at 0,-13.2 h12
Top 3D Body:
  region: -48,16 48,16 48,-16 -48,-16
Mechanical 14:
  text "2" at 31.5,-18 h45
  text "1" at -31.5,-18 h45
Top Assembly:
  text "C0603" at -117,37 h35
3D body: height 150, standoff 0, extent -48,-16 48,16

## C0805 [mm] "C0805"
pads (2):
  rect 1.16x1.47 smd: 1(-0.89,0) 2(0.89,0)
Top Overlay:
  lines w0.2: -0.45,-1.035 -1.37,-1.035 cw(c-1.37,-0.635) -1.77,-0.635 -1.77,0.635 cw(c-1.37,0.635) -1.37,1.035 -0.45,1.035 ; 0.45,-1.035 1.37,-1.035 ccw(c1.37,-0.635) 1.77,-0.635 1.77,0.635 ccw(c1.37,0.635) 1.37,1.035 0.45,1.035
  text "47uF" at 0.488,0.152 h0.3
Top 3D Body:
  region: -1.47,-0.735 1.47,-0.735 1.47,0.735 -1.47,0.735
Mechanical 14:
  text "2" at 1.205,0 h0.79
  text "1" at -0.575,0 h0.79
3D body: height 3.81, standoff 0, extent -1.47,-0.735 1.47,0.735

## CSP20_1R96X1R56X0R66 [mil] "CSP20_1R96X1R56X0R66"
pads (20):
  round 9.45 smd: A1(-23.62,31.5) A2(-7.87,31.5) A3(7.87,31.5) A4(23.62,31.5) B1(-23.62,15.75) B2(-7.87,15.75) B3(7.87,15.75) B4(23.62,15.75) C1(-23.62,0) C2(-7.87,0) C3(7.87,0) C4(23.62,0) D1(-23.62,-15.75) D2(-7.87,-15.75) D3(7.87,-15.75) D4(23.62,-15.75) E1(-23.62,-31.5) E2(-7.87,-31.5) E3(7.87,-31.5) E4(23.62,-31.5)
Top Overlay:
  dashed: -55.12,65.15 -58.96,64.39 -62.21,62.21 -64.39,58.96 -65.15,55.12 -64.39,51.28 -63.66,50.19 -62.21,48.03 -58.96,45.85 -55.12,45.09 -51.28,45.85 -48.03,48.03 -46.58,50.19 -45.85,51.28 -45.09,55.12 -45.85,58.96 -48.03,62.21 -51.28,64.39
  lines w3.94: -50.39,-39.73 -50.39,-58.27 -38.92,-58.27 ; -50.39,-26.98 -50.39,2.45 ; -50.39,16.92 -50.39,35.43 -27.56,58.27 -13.91,58.27 ; -26.42,-58.27 -13.91,-58.27 ; -1.89,-58.27 22.39,-58.27 ; -1.89,58.27 22.39,58.27 ; 35.14,-58.27 50.39,-58.27 50.39,-39.73 ; 35.14,58.27 50.39,58.27 50.39,45.13 ; 50.39,-26.98 50.39,2.45 ; 50.39,16.92 50.39,32.13
  text "TCS4525" at 0,-27.6 h12
Top 3D Body:
  region: -51.18,59.06 -51.18,-59.06 51.18,-59.06 51.18,59.06
  region: -30.16,39.37 -30.16,-39.37 31.5,-39.37 31.5,39.37
Mechanical 14:
  text "A1" at -23.62,23.5 h10
  text "B1" at -23.62,7.75 h10
  text "A3" at 7.87,23.5 h10
  text "A2" at -7.87,23.5 h10
  text "A4" at 23.62,23.5 h10
  text "D1" at -23.62,-23.75 h10
  text "D2" at -7.87,-23.75 h10
  text "E1" at -23.62,-39.5 h10
  text "E2" at -7.87,-39.5 h10
  text "B2" at -7.87,7.75 h10
  text "B3" at 7.87,7.75 h10
  text "B4" at 23.62,7.75 h10
  text "C1" at -23.62,-8 h10
  text "C2" at -7.87,-8 h10
  text "C3" at 7.87,-8 h10
  text "C4" at 23.62,-8 h10
  text "D3" at 7.87,-23.75 h10
  text "D4" at 23.62,-23.75 h10
  text "E3" at 7.87,-39.5 h10
  text "E4" at 23.62,-39.5 h10
3D body: height 150, standoff 0, extent -51.18,-59.06 51.18,59.06
3D body: height 150, standoff 0, extent -30.16,-39.37 31.5,39.37

## DIP-1X2-2P54 [mm] "DIP-1X2-2P54"
pads (2):
  rect 1.5x1.5 hole 0.9: 1(-1.27,0)
  round 1.5 hole 0.9: 2(1.27,0)
Top Overlay:
  lines w0.15: -2.54,-1.27 -2.54,1.27 2.54,1.27 2.54,-1.27 -2.54,-1.27
  text "1X2PIN-M" at 0,-0.823 h0.3
Top 3D Body:
  region: -2.54,-1.27 2.54,-1.27 2.54,1.27 -2.54,1.27
Mechanical 14:
  text "2" at 1.27,-0.254 h0.64
  text "1" at -1.27,-0.254 h0.64
Top Assembly:
  lines w0.025: -2.54,-1.27 -2.54,1.27 2.54,1.27 2.54,-1.27 -2.54,-1.27
  text ".Designator" at -2.54,1.27 h0.89
3D body: height 3.81, standoff 0, extent -2.54,-1.27 2.54,1.27

## FBGA153_0P5_11P5X13 [mil] "FBGA153_0P5_11P5X13"
pads (153):
  round 10 smd: A1(-127.95,127.95) A2(-108.27,127.95) A3(-88.58,127.95) A4(-68.9,127.95) A5(-49.21,127.95) A6(-29.53,127.95) A7(-9.84,127.95) A8(9.84,127.95) A9(29.53,127.95) A10(49.21,127.95) A11(68.9,127.95) A12(88.58,127.95) A13(108.27,127.95) A14(127.95,127.95) B1(-127.95,108.27) B2(-108.27,108.27) B3(-88.58,108.27) B4(-68.9,108.27) B5(-49.21,108.27) B6(-29.53,108.27) B7(-9.84,108.27) B8(9.84,108.27) B9(29.53,108.27) B10(49.21,108.27) B11(68.9,108.27) B12(88.58,108.27) B13(108.27,108.27) B14(127.95,108.27) C1(-127.95,88.58) C2(-108.27,88.58) C3(-88.58,88.58) C4(-68.9,88.58) C5(-49.21,88.58) C6(-29.53,88.58) C7(-9.84,88.58) C8(9.84,88.58) C9(29.53,88.58) C10(49.21,88.58) C11(68.9,88.58) C12(88.58,88.58) C13(108.27,88.58) C14(127.95,88.58) D1(-127.95,68.9) D2(-108.27,68.9) D3(-88.58,68.9) D4(-68.9,68.9) D12(88.58,68.9) D13(108.27,68.9) D14(127.95,68.9) E1(-127.95,49.21) E2(-108.27,49.21) E3(-88.58,49.21) E5(-49.21,49.21) E6(-29.53,49.21) E7(-9.84,49.21) E8(9.84,49.21) E9(29.53,49.21) E10(49.21,49.21) E12(88.58,49.21) E13(108.27,49.21) E14(127.95,49.21) F1(-127.95,29.53) F2(-108.27,29.53) F3(-88.58,29.53) F5(-49.21,29.53) F10(49.21,29.53) F12(88.58,29.53) F13(108.27,29.53) F14(127.95,29.53) G1(-127.95,9.84) G2(-108.27,9.84) G3(-88.58,9.84) G5(-49.21,9.84) G10(49.21,9.84) G12(88.58,9.84) G13(108.27,9.84) G14(127.95,9.84) H1(-127.95,-9.84) H2(-108.27,-9.84) H3(-88.58,-9.84) H5(-49.21,-9.84) H10(49.21,-9.84) H12(88.58,-9.84) H13(108.27,-9.84) H14(127.95,-9.84) J1(-127.95,-29.53) J2(-108.27,-29.53) J3(-88.58,-29.53) J5(-49.21,-29.53) J10(49.21,-29.53) J12(88.58,-29.53) J13(108.27,-29.53) J14(127.95,-29.53) K1(-127.95,-49.21) K2(-108.27,-49.21) K3(-88.58,-49.21) K5(-49.21,-49.21) K6(-29.53,-49.21) K7(-9.84,-49.21) K8(9.84,-49.21) K9(29.53,-49.21) K10(49.21,-49.21) K12(88.58,-49.21) K13(108.27,-49.21) K14(127.95,-49.21) L1(-127.95,-68.9) L2(-108.27,-68.9) L3(-88.58,-68.9) L12(88.58,-68.9) L13(108.27,-68.9) L14(127.95,-68.9) M1(-127.95,-88.58) M2(-108.27,-88.58) M3(-88.58,-88.58) M4(-68.9,-88.58) M5(-49.21,-88.58) M6(-29.53,-88.58) M7(-9.84,-88.58) M8(9.84,-88.58) M9(29.53,-88.58) M10(49.21,-88.58) M11(68.9,-88.58) M12(88.58,-88.58) M13(108.27,-88.58) M14(127.95,-88.58) N1(-127.95,-108.27) N2(-108.27,-108.27) N3(-88.58,-108.27) N4(-68.9,-108.27) N5(-49.21,-108.27) N6(-29.53,-108.27) N7(-9.84,-108.27) N8(9.84,-108.27) N9(29.53,-108.27) N10(49.21,-108.27) N11(68.9,-108.27) N12(88.58,-108.27) N13(108.27,-108.27) N14(127.95,-108.27) P1(-127.95,-127.95) P2(-108.27,-127.95) P3(-88.58,-127.95) P4(-68.9,-127.95) P5(-49.21,-127.95) P6(-29.53,-127.95) P7(-9.84,-127.95) P8(9.84,-127.95) P9(29.53,-127.95) P10(49.21,-127.95) P11(68.9,-127.95) P12(88.58,-127.95) P13(108.27,-127.95) P14(127.95,-127.95)
Top Overlay:
  lines w6: -235.35,-264.87 -235.35,235.77 -206.24,264.87 235.35,264.87 235.35,-264.87 -235.35,-264.87
  text "KLMBG2JETD-B041" at -72,-6 h12
Top 3D Body:
  region: -236.22,-263.78 236.22,-263.78 236.22,263.78 -236.22,263.78
Top Component Center:
  lines w1: -10,0 10,0 ; 0,-10 0,10
Mechanical 14:
  text "E9" at 21.53,49.21 h10
  text "E10" at 37.21,49.21 h10
  text "F10" at 37.21,29.53 h10
  text "K10" at 37.21,-49.21 h10
  text "A1" at -135.95,127.95 h10
  text "A10" at 37.21,127.95 h10
  text "H2" at -116.27,-9.84 h10
  text "H3" at -96.58,-9.84 h10
  text "A11" at 56.9,127.95 h10
  text "H12" at 76.58,-9.84 h10
  text "H13" at 96.27,-9.84 h10
  text "H14" at 115.95,-9.84 h10
  text "J1" at -135.95,-29.53 h10
  text "J2" at -116.27,-29.53 h10
  text "J3" at -96.58,-29.53 h10
  text "A12" at 76.58,127.95 h10
  text "J12" at 76.58,-29.53 h10
  text "J13" at 96.27,-29.53 h10
  text "J14" at 115.95,-29.53 h10
  text "K1" at -135.95,-49.21 h10
  text "K2" at -116.27,-49.21 h10
  text "K3" at -96.58,-49.21 h10
  text "A13" at 96.27,127.95 h10
  text "K12" at 76.58,-49.21 h10
  text "K13" at 96.27,-49.21 h10
  text "A14" at 115.95,127.95 h10
  text "K14" at 115.95,-49.21 h10
  text "L1" at -135.95,-68.9 h10
  text "L2" at -116.27,-68.9 h10
  text "L3" at -96.58,-68.9 h10
  text "B1" at -135.95,108.27 h10
  text "L12" at 76.58,-68.9 h10
  text "L13" at 96.27,-68.9 h10
  text "L14" at 115.95,-68.9 h10
  text "M1" at -135.95,-88.58 h10
  text "M2" at -116.27,-88.58 h10
  text "M3" at -96.58,-88.58 h10
  text "M7" at -17.84,-88.58 h10
  text "M8" at 1.84,-88.58 h10
  text "M9" at 21.53,-88.58 h10
  text "M10" at 37.21,-88.58 h10
  text "M11" at 56.9,-88.58 h10
  text "M12" at 76.58,-88.58 h10
  text "M13" at 96.27,-88.58 h10
  text "M14" at 115.95,-88.58 h10
  text "N1" at -135.95,-108.27 h10
  text "N3" at -96.58,-108.27 h10
  text "N6" at -37.53,-108.27 h10
  text "N7" at -17.84,-108.27 h10
  text "N8" at 1.84,-108.27 h10
  text "N9" at 21.53,-108.27 h10
  text "N10" at 37.21,-108.27 h10
  text "N11" at 56.9,-108.27 h10
  text "N12" at 76.58,-108.27 h10
  text "N13" at 96.27,-108.27 h10
  text "N14" at 115.95,-108.27 h10
  text "P1" at -135.95,-127.95 h10
  text "P2" at -116.27,-127.95 h10
  text "P8" at 1.84,-127.95 h10
  text "P9" at 21.53,-127.95 h10
  text "P11" at 56.9,-127.95 h10
  text "P12" at 76.58,-127.95 h10
  text "P13" at 96.27,-127.95 h10
  text "P14" at 115.95,-127.95 h10
  text "A2" at -116.27,127.95 h10
  text "B7" at -17.84,108.27 h10
  text "B8" at 1.84,108.27 h10
  text "B9" at 21.53,108.27 h10
  text "B10" at 37.21,108.27 h10
  text "B11" at 56.9,108.27 h10
  text "B12" at 76.58,108.27 h10
  text "B13" at 96.27,108.27 h10
  text "B14" at 115.95,108.27 h10
  text "C1" at -135.95,88.58 h10
  text "C3" at -96.58,88.58 h10
  text "C5" at -57.21,88.58 h10
  text "C7" at -17.84,88.58 h10
  text "C8" at 1.84,88.58 h10
  text "C9" at 21.53,88.58 h10
  text "C10" at 37.21,88.58 h10
  text "C11" at 56.9,88.58 h10
  text "C12" at 76.58,88.58 h10
  text "C13" at 96.27,88.58 h10
  text "C14" at 115.95,88.58 h10
  text "D1" at -135.95,68.9 h10
  text "D2" at -116.27,68.9 h10
  text "D3" at -96.58,68.9 h10
  text "D4" at -76.9,68.9 h10
  text "D12" at 76.58,68.9 h10
  text "D13" at 96.27,68.9 h10
  text "D14" at 115.95,68.9 h10
  text "E1" at -135.95,49.21 h10
  text "E2" at -116.27,49.21 h10
  text "E3" at -96.58,49.21 h10
  text "E12" at 76.58,49.21 h10
  text "E13" at 96.27,49.21 h10
  text "E14" at 115.95,49.21 h10
  text "F1" at -135.95,29.53 h10
  text "F2" at -116.27,29.53 h10
  text "F3" at -96.58,29.53 h10
  text "A8" at 1.84,127.95 h10
  text "F12" at 76.58,29.53 h10
  text "F13" at 96.27,29.53 h10
  text "F14" at 115.95,29.53 h10
  text "G1" at -135.95,9.84 h10
  text "G2" at -116.27,9.84 h10
  text "A9" at 21.53,127.95 h10
  text "G12" at 76.58,9.84 h10
  text "G13" at 96.27,9.84 h10
  text "G14" at 115.95,9.84 h10
  text "H1" at -135.95,-9.84 h10
  text "A7" at -17.84,127.95 h10
  text "E5" at -57.21,49.21 h10
  text "E8" at 1.84,49.21 h10
  text "G3" at -96.58,9.84 h10
  text "G10" at 37.21,9.84 h10
  text "K6" at -37.53,-49.21 h10
  text "K7" at -17.84,-49.21 h10
  text "P7" at -17.84,-127.95 h10
  text "P10" at 37.21,-127.95 h10
  text "A4" at -76.9,127.95 h10
  text "A5" at -57.21,127.95 h10
  text "B2" at -116.27,108.27 h10
  text "B3" at -96.58,108.27 h10
  text "B4" at -76.9,108.27 h10
  text "B5" at -57.21,108.27 h10
  text "B6" at -37.53,108.27 h10
  text "M5" at -57.21,-88.58 h10
  text "M6" at -37.53,-88.58 h10
  text "H5" at -57.21,-9.84 h10
  text "K5" at -57.21,-49.21 h10
  text "C2" at -116.27,88.58 h10
  text "C6" at -37.53,88.58 h10
  text "M4" at -76.9,-88.58 h10
  text "N4" at -76.9,-108.27 h10
  text "P3" at -96.58,-127.95 h10
  text "P5" at -57.21,-127.95 h10
  text "E6" at -37.53,49.21 h10
  text "F5" at -57.21,29.53 h10
  text "J10" at 37.21,-29.53 h10
  text "K9" at 21.53,-49.21 h10
  text "C4" at -76.9,88.58 h10
  text "N5" at -57.21,-108.27 h10
  text "P6" at -37.53,-127.95 h10
  text "P4" at -76.9,-127.95 h10
  text "G5" at -57.21,9.84 h10
  text "J5" at -57.21,-29.53 h10
  text "K8" at 1.84,-49.21 h10
  text "E7" at -17.84,49.21 h10
  text "H10" at 37.21,-9.84 h10
  text "N2" at -116.27,-108.27 h10
  text "A6" at -37.53,127.95 h10
  text "A3" at -96.58,127.95 h10
Top Assembly:
  circle w6: c-188.98,220.47 r26.41
  lines w6: -228.35,-257.87 -228.35,232.87 -203.35,257.87 228.35,257.87 228.35,-257.87 -228.35,-257.87
3D body: height 150, standoff 0, extent -236.22,-263.78 236.22,263.78

## L0402 [mm] "L0402"
pads (2):
  rect 0.599x0.599 smd: 1(-0.5,0) 2(0.5,0)
Top Overlay:
  lines w0.102: -0.94,-0.432 0.94,-0.432 0.94,0.432 -0.94,0.432 -0.94,-0.432
  text "120R 100MHz" at -1.341,0.152 h0.3
Top 3D Body:
  region: 0.94,0.432 0.94,-0.432 -0.94,-0.432 -0.94,0.432
Mechanical 14:
  text "2" at 0.246,0 h0.64
  text "1" at -0.754,0 h0.64
Top Assembly:
  dashed: -0.94,-0.432 -0.94,0.432 0.94,0.432 0.94,-0.432
3D body: height 3.81, standoff 0, extent -0.94,-0.432 0.94,0.432

## L2520 [mil] "L2520"
pads (2):
  rect 44x80 smd: 1(-37.75,0) 2(37.75,0)
Top Overlay:
  lines w6: -67.68,-48.15 -67.68,47.92 67.67,47.92 67.67,-48.15 -67.67,-48.15 -67.68,-48.15
  text "2.2uH" at 0,18 h12
Top 3D Body:
  region: -65,-45 65,-45 65,45 -65,45
Mechanical 14:
  text "1" at -37.75,4.72 h11.81
  text "2" at 37.75,4.72 h11.81
3D body: height 150, standoff 0, extent -65,-45 65,45

## L4520 [mm] "L4520"
pads (2):
  rect 1.4x2.3 smd: 1(-1.803,-0.003) 2(1.798,-0.003)
Top Overlay:
  lines w0.15: -2.303,-1.453 -2.303,-2.202 2.297,-2.202 2.297,-1.453 ; -2.303,1.448 -2.303,2.197 2.297,2.197 2.297,1.448
  text "3.3uH" at -0.61,-0.152 h0.3
Top 3D Body:
  lines w0.025: -2.303,-2.202 -2.303,2.202 2.303,2.202 2.303,-2.202 -2.303,-2.202
Mechanical 14:
  text "2" at 1.544,-0.003 h0.64
  text "1" at -2.057,-0.003 h0.64
Top Assembly:
  lines w0.15: -2.303,-1.453 -2.303,-2.202 2.297,-2.202 2.297,-1.453 ; -2.303,1.448 -2.303,2.197 2.297,2.197 2.297,1.448

## PTH_M2R5 [mm] "PTH_M2R5"
pads (1):
  round 5.2 hole 2.6: 1(0,0)
Top Overlay:
  text "PTH_M2.5" at -0.975,-0.152 h0.3
Top 3D Body:
  region: 2.708,0 2.675,0.424 2.576,0.837 2.413,1.23 2.191,1.592 1.915,1.915 1.592,2.191 1.23,2.413 0.837,2.576 0.424,2.675 0,2.708 -0.424,2.675 -0.837,2.576 -1.23,2.413 -1.35,2.339 -1.592,2.191 -1.915,1.915 -2.191,1.592 -2.413,1.23 -2.576,0.837 -2.675,0.424 -2.708,0 -2.675,-0.424 -2.576,-0.837 -2.413,-1.23 -2.191,-1.592 -1.915,-1.915 -1.592,-2.191 -1.35,-2.339 -1.23,-2.413 -0.837,-2.576 -0.424,-2.675 0,-2.708 0.424,-2.675 0.837,-2.576 1.23,-2.413 1.592,-2.191 1.915,-1.915 2.191,-1.592 2.413,-1.23 2.576,-0.837 2.675,-0.424
Mechanical 14:
  text "1" at -0.254,0 h0.64
3D body: height 3.81, standoff 0, extent -2.708,-2.708 2.708,2.708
